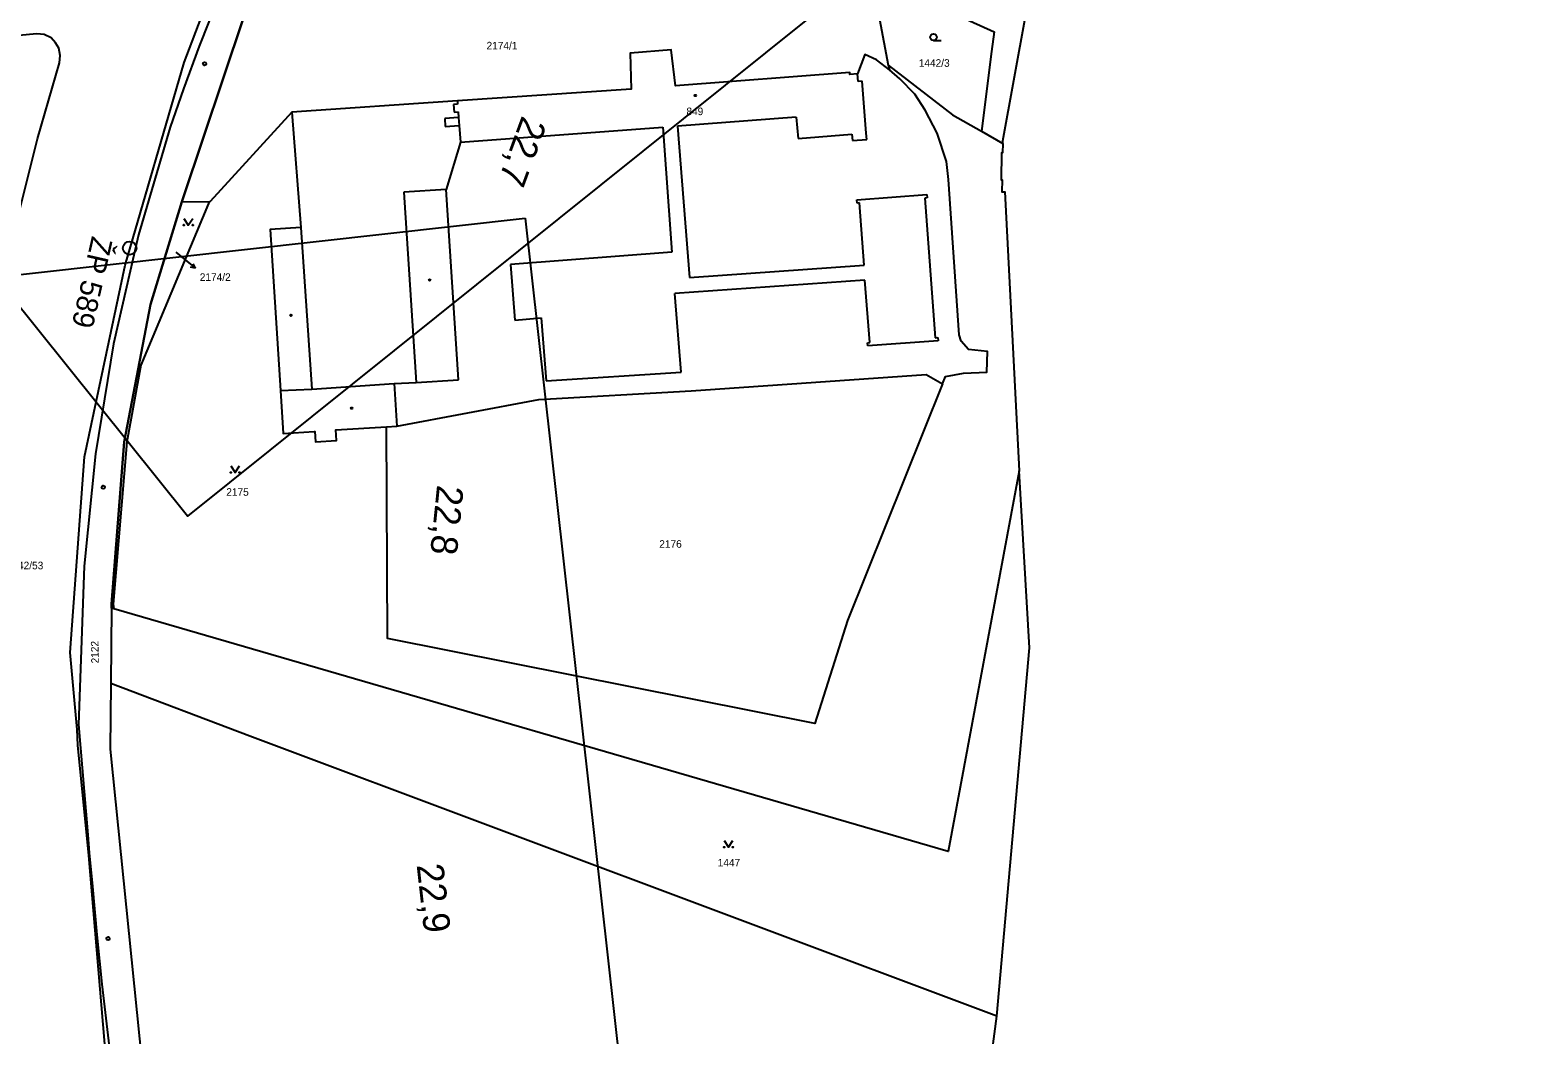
# Model space of a CAD drawing. Extents: x -793666 to -785424, y -1118958 to -1108761.
# Drawn here: x -792633.4 to -792294.2, y -1110388.2 to -1110162.1 of the extents above; entities that cross this region are included whole.
import ezdxf

# ---------------------------------------------------------------- set-up
doc = ezdxf.new("R2010")
doc.units = 0
for name, color, linetype in [('1', 7, 'Continuous'), ('1_2000 - úřady', 7, 'Continuous'), ('Hranice parcel', 7, 'Continuous'), ('Parcelní čísla', 7, 'Continuous'), ('Pop  PČ popisy', 7, 'Continuous'), ('Vnitřní kresba', 7, 'Continuous'), ('Vrstva 53', 7, 'Continuous'), ('Vrstva 63', 7, 'Continuous'), ('Vrstva 7', 7, 'Continuous'), ('Značky budov', 7, 'Continuous'), ('Značky kultur', 7, 'Continuous')]:
    doc.layers.add(name, color=color, linetype=linetype)

msp = doc.modelspace()

# ---------------------------------------------------------------- linework, layer by layer
at = {"layer": '1'}
msp.add_line((-792617.24, -1110376.79), (-792613.96, -1110405.45), dxfattribs=at)
for points in [[(-792520.18, -1110042.35), (-792525.76, -1110048.77), (-792536.81, -1110062.27), (-792540.95, -1110067.66), (-792549.85, -1110079.92), (-792555.36, -1110088.05), (-792568.48, -1110109.4), (-792580.36, -1110131.61), (-792584.74, -1110140.75), (-792587.25, -1110146.23), (-792591.15, -1110155.22), (-792591.33, -1110155.64), (-792593.22, -1110160.27), (-792595.37, -1110165.76), (-792598.91, -1110175.34), (-792601.89, -1110184), (-792609.05, -1110208.22), (-792614.63, -1110232.71), (-792618.7, -1110257.45), (-792621.24, -1110282.73), (-792622.5, -1110318.4)], [(-792622.5, -1110318.4), (-792620.42, -1110343.15), (-792620.09, -1110347.24), (-792619.38, -1110354.81), (-792618.38, -1110365.71), (-792617.24, -1110376.79)]]:
    msp.add_lwpolyline(points, dxfattribs=at)
for centre in [(-792594.15, -1110169.69), (-792616.95, -1110264.99), (-792615.87, -1110366.52)]:
    msp.add_circle(centre, 0.375, dxfattribs=at)
at = {"layer": '1_2000 - úřady'}
for points in [[(-791938.08, -1109742.36), (-792598.01, -1110271.46), (-792786.15, -1110036.8), (-792126.22, -1109507.7)], [(-792522.06, -1110204.41), (-792422.02, -1111099.6), (-792720.93, -1111133), (-792820.96, -1110237.81)]]:
    msp.add_lwpolyline(points, close=True, dxfattribs=at)
at = {"layer": 'Hranice parcel'}
for p, q in [((-792445.06, -1110144.98), (-792440.37, -1110170.05)), ((-792417.12, -1110166.95), (-792419.42, -1110184.88)), ((-792440.37, -1110170.05), (-792440.09, -1110171.09)), ((-792574.54, -1110180.58), (-792592.91, -1110200.68)), ((-792419.42, -1110184.88), (-792414.6, -1110187.62)), ((-792599.26, -1110200.78), (-792592.91, -1110200.68)), ((-792408.61, -1110301.1), (-792410.9, -1110261.26)), ((-792615.1, -1110292.2), (-792615.25, -1110309.12)), ((-792614.55, -1110292.36), (-792615.1, -1110292.2)), ((-792415.98, -1110384.02), (-792408.61, -1110301.1))]:
    msp.add_line(p, q, dxfattribs=at)
for points in [[(-792443.61, -1110144.37), (-792439.23, -1110152.21), (-792416.55, -1110162.51), (-792417.12, -1110166.95)], [(-792414.6, -1110187.62), (-792414.59, -1110187.07), (-792406.86, -1110144.6)], [(-792614.81, -1110411.53), (-792620.21, -1110347.82), (-792622.68, -1110323), (-792622.83, -1110319.49), (-792624.38, -1110302.15), (-792621.16, -1110258.14), (-792612.04, -1110215.02), (-792598.72, -1110169.4), (-792594.35, -1110157.78)], [(-792599.26, -1110200.78), (-792598.98, -1110199.86), (-792585.44, -1110159.39), (-792584.67, -1110156.97)], [(-792636.2, -1110204.31), (-792631.71, -1110186.61), (-792626.82, -1110169.51), (-792626.68, -1110167.87), (-792626.94, -1110166.21), (-792627.67, -1110165.03), (-792628.66, -1110163.9), (-792630.27, -1110163.16), (-792631.9, -1110162.99), (-792650.59, -1110164.71)], [(-792440.09, -1110171.09), (-792442.98, -1110168.82), (-792445.67, -1110167.64), (-792447.27, -1110171.97), (-792449, -1110172.1), (-792449.03, -1110171.7), (-792488.19, -1110174.66), (-792489.22, -1110166.57), (-792498.43, -1110167.35), (-792498.19, -1110175.42), (-792537.3, -1110178.08), (-792574.54, -1110180.58)], [(-792440.37, -1110170.05), (-792425.92, -1110181.18), (-792419.42, -1110184.88)], [(-792428.18, -1110241.75), (-792427.47, -1110240.1), (-792423.46, -1110239.3), (-792418.19, -1110239.06), (-792418.07, -1110234.46), (-792422.34, -1110233.99), (-792423.93, -1110232.15), (-792424.38, -1110230.66), (-792426.83, -1110195.76), (-792427.28, -1110191.69), (-792429.33, -1110185.29), (-792432.06, -1110180.14), (-792434.4, -1110176.53), (-792437.76, -1110173.1), (-792440.09, -1110171.09)], [(-792574.54, -1110180.58), (-792572.51, -1110206.56), (-792579.43, -1110206.98), (-792577.11, -1110243.19), (-792576.49, -1110252.87), (-792569.52, -1110252.42), (-792569.38, -1110252.41), (-792569.21, -1110254.77), (-792564.45, -1110254.49), (-792564.62, -1110252.1), (-792553.22, -1110251.37)], [(-792414.6, -1110187.62), (-792414.65, -1110189.75), (-792414.87, -1110189.75), (-792414.99, -1110195.8), (-792414.76, -1110195.8), (-792414.82, -1110198.52), (-792414.13, -1110198.54), (-792410.9, -1110261.26)], [(-792615.1, -1110292.2), (-792615.1, -1110291.3), (-792612.21, -1110254.77), (-792606.33, -1110223.88), (-792599.26, -1110200.78)], [(-792592.91, -1110200.68), (-792593.31, -1110201.12), (-792608.53, -1110237.49), (-792611.62, -1110254.8), (-792614.73, -1110291.32), (-792614.55, -1110292.36)], [(-792553.22, -1110251.37), (-792550.89, -1110251.22), (-792519, -1110245.23), (-792484.69, -1110243.32), (-792431.83, -1110239.64), (-792428.18, -1110241.75)], [(-792428.18, -1110241.75), (-792449.51, -1110294.97), (-792456.91, -1110318.15), (-792552.98, -1110299.01), (-792553.22, -1110251.37)], [(-792410.9, -1110261.26), (-792426.87, -1110346.94), (-792614.55, -1110292.36)], [(-792615.25, -1110309.12), (-792615.38, -1110323.92), (-792608.17, -1110395.02), (-792606.36, -1110410.71)], [(-792415.98, -1110384.02), (-792584, -1110320.97), (-792615.25, -1110309.12)], [(-792447.39, -1110553.73), (-792435.3, -1110531.31), (-792423.63, -1110442.31), (-792423.05, -1110437.93), (-792415.98, -1110384.02)]]:
    msp.add_lwpolyline(points, dxfattribs=at)
at = {"layer": 'Pop  PČ popisy'}
for p, q in [((-792600.65, -1110212.11), (-792598.56, -1110213.83)), ((-792598.56, -1110213.83), (-792596.23, -1110215.72)), ((-792596.23, -1110215.72), (-792597.32, -1110215.48)), ((-792596.23, -1110215.72), (-792596.69, -1110214.7))]:
    msp.add_line(p, q, dxfattribs=at)
at = {"layer": 'Vnitřní kresba'}
for p, q in [((-792447.15, -1110173.71), (-792447.27, -1110171.97)), ((-792446.2, -1110173.63), (-792447.15, -1110173.71)), ((-792445.3, -1110185.31), (-792446.2, -1110173.63)), ((-792537.24, -1110178.81), (-792538.15, -1110178.88)), ((-792538.15, -1110178.88), (-792538.02, -1110180.6)), ((-792537.3, -1110178.08), (-792537.24, -1110178.81)), ((-792537.02, -1110181.8), (-792540.15, -1110182.03)), ((-792540.15, -1110182.03), (-792540.01, -1110183.86)), ((-792538.02, -1110180.6), (-792537.12, -1110180.53)), ((-792537.12, -1110180.53), (-792537.02, -1110181.8)), ((-792537.02, -1110181.8), (-792536.89, -1110183.63)), ((-792461.08, -1110181.72), (-792487.75, -1110183.72)), ((-792461.08, -1110181.72), (-792460.6, -1110186.55)), ((-792540.01, -1110183.86), (-792536.89, -1110183.63)), ((-792536.89, -1110183.63), (-792536.61, -1110187.38)), ((-792536.61, -1110187.38), (-792491.07, -1110183.97)), ((-792491.07, -1110183.97), (-792489.04, -1110212.1)), ((-792487.75, -1110183.72), (-792485.07, -1110217.77)), ((-792460.6, -1110186.55), (-792448.55, -1110185.58)), ((-792448.55, -1110185.58), (-792448.43, -1110187.01)), ((-792445.19, -1110186.74), (-792445.3, -1110185.31)), ((-792536.61, -1110187.38), (-792539.82, -1110198.03)), ((-792448.43, -1110187.01), (-792445.19, -1110186.74)), ((-792539.82, -1110198.03), (-792549.37, -1110198.62)), ((-792549.37, -1110198.62), (-792546.55, -1110241.4)), ((-792537.07, -1110240.81), (-792539.82, -1110198.03)), ((-792447.44, -1110200.34), (-792431.67, -1110199.14)), ((-792431.67, -1110199.14), (-792431.62, -1110199.88)), ((-792447.38, -1110201.06), (-792447.44, -1110200.34)), ((-792446.84, -1110201.01), (-792447.38, -1110201.06)), ((-792445.81, -1110214.99), (-792446.84, -1110201.01)), ((-792431.62, -1110199.88), (-792432.17, -1110199.92)), ((-792432.17, -1110199.92), (-792429.8, -1110231.35)), ((-792572.51, -1110206.56), (-792570.05, -1110242.91)), ((-792489.04, -1110212.1), (-792525.33, -1110214.85)), ((-792525.33, -1110214.85), (-792524.39, -1110227.43)), ((-792485.07, -1110217.77), (-792445.81, -1110214.99)), ((-792445.64, -1110218.39), (-792488.37, -1110221.41)), ((-792444.53, -1110232.45), (-792445.64, -1110218.39)), ((-792486.96, -1110239.12), (-792488.37, -1110221.41)), ((-792524.39, -1110227.43), (-792518.43, -1110226.86)), ((-792518.43, -1110226.86), (-792517.34, -1110241.06)), ((-792445.05, -1110232.49), (-792444.53, -1110232.45)), ((-792444.99, -1110233.2), (-792445.05, -1110232.49)), ((-792429.15, -1110232.03), (-792444.99, -1110233.2)), ((-792429.8, -1110231.35), (-792429.2, -1110231.3)), ((-792429.2, -1110231.3), (-792429.15, -1110232.03)), ((-792517.34, -1110241.06), (-792486.96, -1110239.12)), ((-792577.11, -1110243.19), (-792570.05, -1110242.91)), ((-792570.05, -1110242.91), (-792551.5, -1110241.68)), ((-792551.5, -1110241.68), (-792546.55, -1110241.4)), ((-792551.5, -1110241.68), (-792550.89, -1110251.22)), ((-792546.55, -1110241.4), (-792537.07, -1110240.81))]:
    msp.add_line(p, q, dxfattribs=at)
at = {"layer": 'Vrstva 53'}
msp.add_lwpolyline([(-792585.44, -1110159.39), (-792598.98, -1110199.86), (-792599.26, -1110200.78), (-792606.33, -1110223.88), (-792612.21, -1110254.77), (-792615.1, -1110291.3), (-792615.1, -1110292.2), (-792615.25, -1110309.12), (-792615.38, -1110323.92), (-792608.17, -1110395.02), (-792606.36, -1110410.71), (-792608.74, -1110410.94), (-792608.68, -1110411.53), (-792612.94, -1110412.04), (-792613.01, -1110411.35), (-792614.81, -1110411.53), (-792620.21, -1110347.82), (-792622.68, -1110323), (-792622.83, -1110319.49), (-792624.38, -1110302.15), (-792621.16, -1110258.14), (-792612.04, -1110215.02), (-792598.72, -1110169.4), (-792594.35, -1110157.78)], dxfattribs=at)
at = {"layer": 'Vrstva 63'}
msp.add_line((-792611.1, -1110211.18), (-792610.9, -1110211.18), dxfattribs=at)
msp.add_circle((-792611, -1110211.18), 1.51, dxfattribs=at)
at = {"layer": 'Značky budov'}
for centre in [(-792483.76, -1110176.85), (-792543.51, -1110218.36), (-792574.73, -1110226.33), (-792561.05, -1110247.19)]:
    msp.add_circle(centre, 0.175, dxfattribs=at)
at = {"layer": 'Značky kultur'}
msp.add_line((-792430.2, -1110164.49), (-792428.45, -1110164.49), dxfattribs=at)
for points in [[(-792598.82, -1110204.49), (-792597.82, -1110205.99), (-792596.82, -1110204.49)], [(-792588.28, -1110260.17), (-792587.28, -1110261.67), (-792586.28, -1110260.17)], [(-792477.3, -1110344.46), (-792476.3, -1110345.96), (-792475.3, -1110344.46)]]:
    msp.add_lwpolyline(points, dxfattribs=at)
for centre, radius in [((-792430.2, -1110163.74), 0.75), ((-792598.82, -1110205.99), 0.1), ((-792596.82, -1110205.99), 0.1), ((-792588.28, -1110261.67), 0.1), ((-792586.28, -1110261.67), 0.1), ((-792477.3, -1110345.96), 0.1), ((-792475.3, -1110345.96), 0.1)]:
    msp.add_circle(centre, radius, dxfattribs=at)

# ---------------------------------------------------------------- texts
at = {"layer": 'Parcelní čísla'}
for s, p in [('2174/1', (-792530.73, -1110166.48)), ('1442/3', (-792433.51, -1110170.39)), ('849', (-792485.77, -1110181.27)), ('2174/2', (-792595.24, -1110218.56)), ('2175', (-792589.28, -1110266.9)), ('2176', (-792491.88, -1110278.6)), ('1442/53', (-792638.66, -1110283.44)), ('1447', (-792478.73, -1110350.29))]:
    msp.add_text(s, height=1.7, dxfattribs=at).set_placement(p)
msp.add_text('2122', height=1.7, rotation=91, dxfattribs=at).set_placement((-792617.95, -1110304.6))
at = {"layer": 'Vrstva 63'}
msp.add_text('ŽP 589', height=4.8, rotation=257.1565, dxfattribs=at).set_placement((-792619.47, -1110208.32))
at = {"layer": 'Vrstva 7'}
for s, rotation, p in [('22,7', 249.6626, (-792522.71, -1110181.2)), ('22,8', 264.2533, (-792541.84, -1110264.35)), ('22,9', 276.3659, (-792546.46, -1110349.98))]:
    msp.add_text(s, height=6, rotation=rotation, dxfattribs=at).set_placement(p)

doc.saveas('drawing.dxf')
